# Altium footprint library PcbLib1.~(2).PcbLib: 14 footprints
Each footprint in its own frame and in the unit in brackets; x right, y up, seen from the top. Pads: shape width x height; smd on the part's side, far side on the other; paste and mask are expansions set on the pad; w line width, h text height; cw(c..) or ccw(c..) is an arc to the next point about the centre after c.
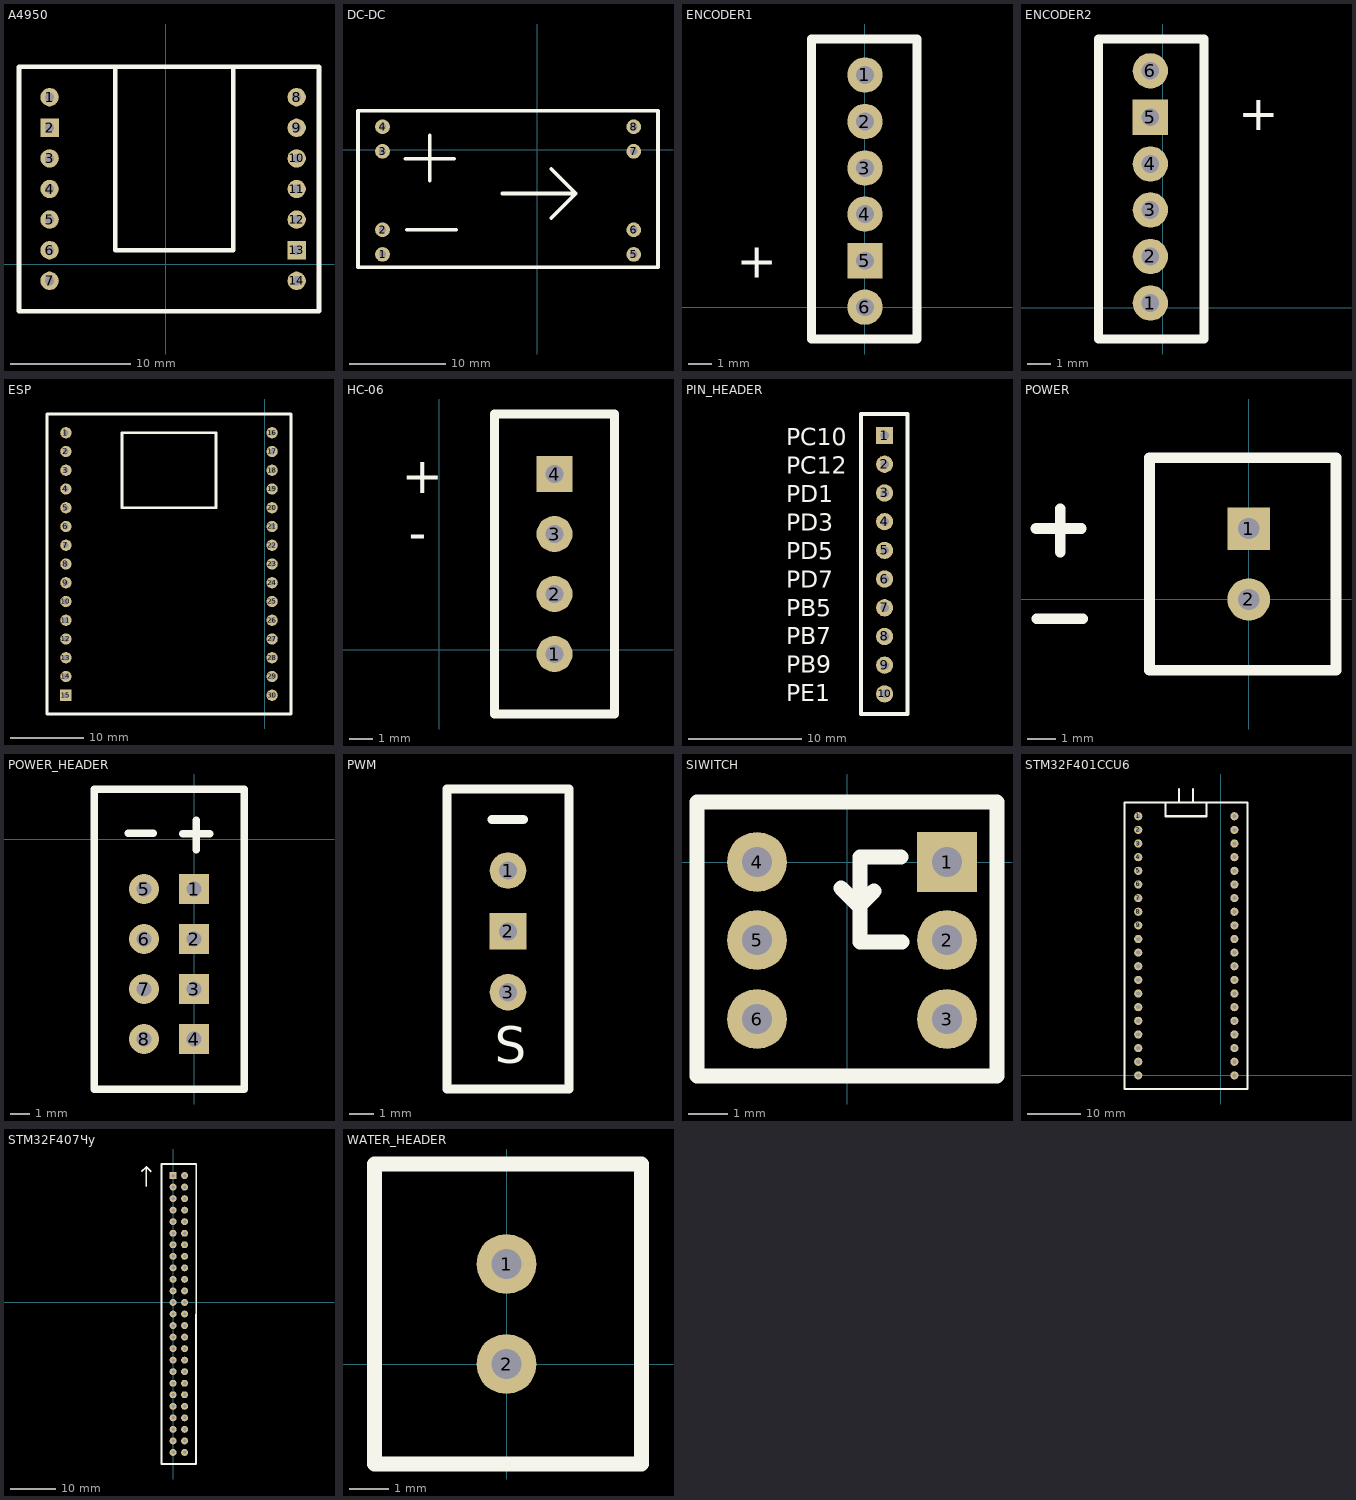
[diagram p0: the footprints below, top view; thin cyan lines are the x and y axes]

## A4950 [mil]
pads (14):
  round 60 hole 30: 1(-380,545) 3(-380,345) 4(-380,245) 5(-380,145) 6(-380,45) 7(-380,-55) 8(427,545) 9(427,445) 10(427,345) 11(427,245) 12(427,145) 14(427,-55)
  rect 60x60 hole 30: 2(-380,445) 13(427,45)
Top Overlay:
  lines w15: -165,645 -165,45 220,45 220,645 ; -480,-155 -480,645 500,645 500,-155 -480,-155

## DC-DC [mil]
pads (8):
  round 60 hole 30: 1(-631,-426) 2(-631,-326) 3(-631,-6) 4(-631,94) 5(393,-426) 6(393,-326) 7(393,-6) 8(393,94)
Top Overlay:
  lines w15: -538,-36 -338,-36 ; -531,-326 -331,-326 ; -438,-126 -438,-106 -438,34 -438,60 ; -143,-178 157,-178 ; 57,-278 157,-178 ; 57,-78 157,-178 ; -731,-479 -731,160 492,160 492,-103 492,-479 -731,-479

## ENCODER1 [mil]
pads (6):
  round 60 hole 30: 1(0,394) 2(0,315) 3(0,236) 4(0,158) 6(0,0)
  rect 60x60 hole 30: 5(0,79)
Top Overlay:
  lines w15: -91,-54 -91,455 88,455 88,-54 -91,-54
  text "+" at -149,50 h60

## ENCODER2 [mil]
pads (6):
  round 60 hole 30: 1(-21,8) 2(-21,87) 3(-21,166) 4(-21,244) 6(-21,402)
  rect 60x60 hole 30: 5(-21,323)
Top Overlay:
  lines w15: -109,-53 70,-53 70,456 -109,456 -109,-53
  text "+" at 128,352 h60

## ESP [mil]
pads (30):
  round 60 hole 30: 1(-1061,2034) 2(-1061,1934) 3(-1061,1834) 4(-1061,1734) 5(-1061,1634) 6(-1061,1534) 7(-1061,1434) 8(-1061,1334) 9(-1061,1234) 10(-1061,1134) 11(-1061,1034) 12(-1061,934) 13(-1061,834) 14(-1061,734) 16(39,2034) 17(39,1934) 18(39,1834) 19(39,1734) 20(39,1634) 21(39,1534) 22(39,1434) 23(39,1334) 24(39,1234) 25(39,1134) 26(39,1034) 27(39,934) 28(39,834) 29(39,734) 30(39,634)
  rect 60x60 hole 30: 15(-1061,634)
Top Overlay:
  lines w15: -1161,534 139,534 139,2134 -1161,2134 -1161,534 ; -761,1634 -761,2034 -261,2034 -261,1634 -761,1634

## HC-06 [mil]
pads (4):
  round 60 hole 30: 1(192,-7) 2(192,93) 3(192,193)
  rect 60x60 hole 30: 4(192,293)
Top Overlay:
  lines w15: 92,-107 292,-107 292,393 92,393 92,-107
  text "+" at -63,261 h60
  text "-" at -51,166 h60

## PIN_HEADER [mil]
pads (10):
  rect 60x60 hole 30: 1(10306,19392)
  round 60 hole 30: 2(10306,19292) 3(10306,19192) 4(10306,19092) 5(10306,18992) 6(10306,18892) 7(10306,18792) 8(10306,18692) 9(10306,18592) 10(10306,18492)
Top Overlay:
  lines w15: 10224,18422 10386,18422 10386,19467 10224,19467 10224,18422
  text "PC10" at 9964,19358 h60
  text "PC12" at 9964,19258.89 h60
  text "PD1" at 9964,19159.78 h60
  text "PD3" at 9964,19060.67 h60
  text "PD5" at 9964,18961.56 h60
  text "PD7" at 9964,18862.44 h60
  text "PB5" at 9964,18763.33 h60
  text "PB9" at 9964,18565.11 h60
  text "PE1" at 9964,18466 h60
  text "PB7" at 9964,18664.22 h60

## POWER [mil]
pads (2):
  rect 60x60 hole 30: 1(0,100)
  round 60 hole 30: 2(0,0)
Top Overlay:
  lines w15: -300,100 -236,100 ; -299,-27 -234,-27 ; -266,67 -266,128 ; -140,-100 -140,200 123,200 123,-100 -140,-100

## POWER_HEADER [mil]
pads (8):
  rect 60x60 hole 30: 1(0,-100) 2(0,-200) 3(0,-300) 4(0,-400)
  round 60 hole 30: 5(-100,-100) 6(-100,-200) 7(-100,-300) 8(-100,-400)
Top Overlay:
  lines w15: -132,12 -82,12 ; -23,11 31,11 ; 4,-21 4,38 ; -200,-500 100,-500 100,100 -200,100 -200,-500

## PWM [mil]
pads (3):
  round 60 hole 30: 1(-700,1500) 3(-700,1300)
  rect 60x60 hole 30: 2(-700,1400)
Top Overlay:
  lines w15: -726,1584 -675,1584 ; -800,1141 -600,1141 -600,1634 -800,1634 -800,1141
  text "S" at -722,1183 h60

## SIWITCH [mil]
pads (6):
  rect 60x60 hole 30: 1(100,0)
  round 60 hole 30: 2(100,-78) 3(100,-157) 4(-90,0) 5(-90,-78) 6(-90,-157)
Top Overlay:
  lines w15: -90,60 90,60 150,60 ; -6,-26 12,-44 27,-29 ; 54,5 13,5 13,-80 55,-80 ; 150,60 -120,60 -150,60 -150,-214 150,-214 150,60

## STM32F401CCU6 [mil]
pads (40):
  round 60 hole 30: 1(-605,1900) 2(-605,1800) 3(-605,1700) 4(-605,1600) 5(-605,1500) 6(-605,1400) 7(-605,1300) 8(-605,1200) 9(-605,1100) 10(-605,1000) 11(-605,900) 12(-605,800) 13(-605,700) 14(-605,600) 15(-605,500) 16(-605,400) 17(-605,300) 18(-605,200) 19(-605,100) 20(-605,0) 21(100,1900) 22(100,1800) 23(100,1700) 24(100,1600) 25(100,1500) 26(100,1400) 27(100,1300) 28(100,1200) 29(100,1100) 30(100,1000) 31(100,900) 32(100,800) 33(100,700) 34(100,600) 35(100,500) 36(100,400) 37(100,300) 38(100,200) 39(100,100) 40(100,0)
Top Overlay:
  lines w15: -405,2000 -405,1900 -105,1900 -105,2000 ; -305,2000 -305,2100 ; -205,2000 -205,2100 ; -705,-100 -705,0 -705,2000 195,2000 195,1900 195,-100 -705,-100

## STM32F407Чу [mil]
pads (50):
  rect 60x60 hole 30: 1(0,1100)
  round 60 hole 30: 2(0,1000) 3(0,900) 4(0,800) 5(0,700) 6(0,600) 7(0,500) 8(0,400) 9(0,300) 10(0,200) 11(0,100) 12(0,0) 13(0,-100) 14(0,-200) 15(0,-300) 16(0,-400) 17(0,-500) 18(0,-600) 19(0,-700) 20(0,-800) 21(0,-900) 22(0,-1000) 23(100,1100) 24(100,1000) 25(100,900) 26(100,800) 27(100,700) 28(100,600) 29(100,500) 30(100,400) 31(100,300) 32(100,200) 33(100,100) 34(100,0) 35(100,-100) 36(100,-200) 37(100,-300) 38(100,-400) 39(100,-500) 40(100,-600) 41(100,-700) 42(100,-800) 43(100,-900) 44(100,-1000) 45(0,-1100) 46(0,-1200) 47(0,-1300) 48(100,-1100) 49(100,-1200) 50(100,-1300)
Top Overlay:
  lines w15: -270,1137 -233,1174 -233,1175 ; -233,1009 -233,1175 ; -194,1136 -233,1175 ; -100,-1400 200,-1400 200,1200 100,1200 -100,1200 -100,-1400

## WATER_HEADER [mil]
pads (2):
  round 60 hole 30: 1(0,100) 2(0,0)
Top Overlay:
  lines w15: -132,-100 -132,200 135,200 135,-100 -132,-100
